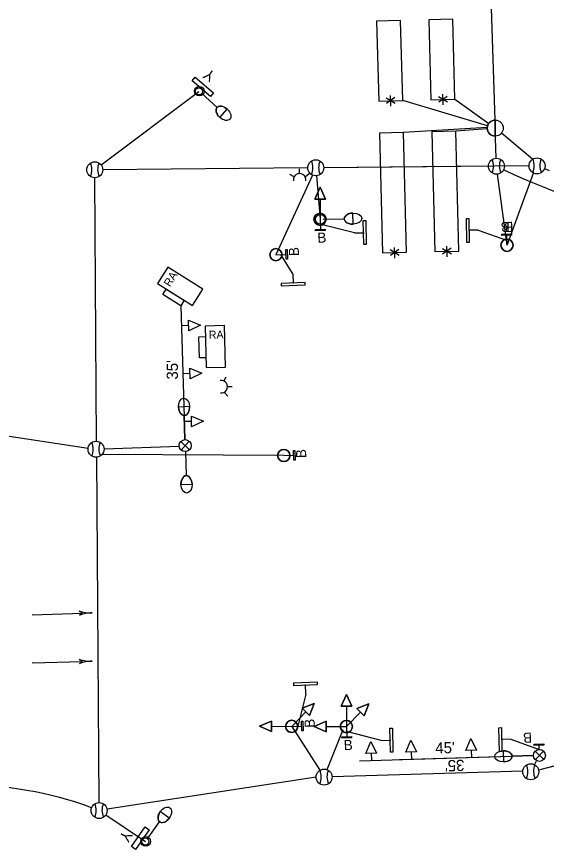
# Model space of a CAD drawing. Extents: x 596176 to 605330, y 332416 to 402398.
# Drawn here: x 603956.7 to 604089.1, y 339261.6 to 339469.9 of the extents above; entities that cross this region are included whole.
import ezdxf

# ---------------------------------------------------------------- set-up
doc = ezdxf.new("R2010")
doc.units = 0
for name, color, linetype in [('P_LTG', 7, 'Continuous'), ('P_SIG', 7, 'Continuous'), ('P_SIG_Bold', 7, 'Continuous'), ('P_SIG_Conduit', 7, 'Continuous'), ('P_SIG_Loops', 7, 'Continuous')]:
    doc.layers.add(name, color=color, linetype=linetype)

# ---------------------------------------------------------------- blocks, each defined once
blk = doc.blocks.new('LUMINAIRES')
at = {"layer": 'P_LTG'}
for p, q in [((4.32, 25.12), (-4.14, 25.12)), ((0.05, 2.3), (0.05, 18.44))]:
    blk.add_line(p, q, dxfattribs=at)
blk.add_circle((0.05, 0.15), 3.68, dxfattribs=at)
blk.add_ellipse((0.09, 25.12), major_axis=(0, 6.65), ratio=0.636439, dxfattribs=at)
blk.add_ellipse((0.09, 25.12), major_axis=(0, 6.65), ratio=0.636439, start_param=1.570796, end_param=4.712389, dxfattribs=at)
blk = doc.blocks.new('_U314')
at = {"layer": 'P_LTG'}
for p, q in [((4.32, 25.12), (-4.14, 25.12)), ((0.05, 2.3), (0.05, 18.44))]:
    blk.add_line(p, q, dxfattribs=at)
blk.add_ellipse((0.09, 25.12), major_axis=(0, 6.65), ratio=0.636439, dxfattribs=at)
blk.add_ellipse((0.09, 25.12), major_axis=(0, 6.65), ratio=0.636439, start_param=1.570796, end_param=4.712389, dxfattribs=at)
blk = doc.blocks.new('_U318')
at = {"layer": 'P_LTG'}
for p, q in [((4.32, 25.12), (-4.14, 25.12)), ((0.05, 2.3), (0.05, 18.44))]:
    blk.add_line(p, q, dxfattribs=at)
blk.add_ellipse((0.09, 25.12), major_axis=(0, 6.65), ratio=0.636439, dxfattribs=at)
blk.add_ellipse((0.09, 25.12), major_axis=(0, 6.65), ratio=0.636439, start_param=1.570796, end_param=4.712389, dxfattribs=at)

msp = doc.modelspace()

# ---------------------------------------------------------------- linework, layer by layer
at = {"layer": 'P_LTG'}
for p, q in [((603999.95, 339372.35), (603997.17, 339372.26)), ((603999.95, 339372.35), (603997.17, 339372.26)), ((603998.8, 339364.11), (603998.61, 339370.17)), ((603998.8, 339364.11), (603998.61, 339370.17)), ((603998.9, 339361.11), (603999.13, 339355.11)), ((603998.9, 339361.11), (603999.13, 339355.11)), ((603997.81, 339352.87), (604000.58, 339352.97)), ((603997.81, 339352.87), (604000.58, 339352.97))]:
    msp.add_line(p, q, dxfattribs=at)
for centre, major_axis in [((603998.56, 339372.3), (-0.07, 2.18)), ((603998.56, 339372.3), (-0.07, 2.18)), ((603999.19, 339352.92), (0.08, -2.18)), ((603999.19, 339352.92), (0.08, -2.18))]:
    msp.add_ellipse(centre, major_axis=major_axis, ratio=0.636439, dxfattribs=at)
for centre, major_axis in [((603998.56, 339372.3), (-0.07, 2.18)), ((603998.56, 339372.3), (-0.07, 2.18)), ((603999.19, 339352.92), (0.08, -2.18)), ((603999.19, 339352.92), (0.08, -2.18))]:
    msp.add_ellipse(centre, major_axis=major_axis, ratio=0.636439, start_param=1.570796, end_param=4.712389, dxfattribs=at)
at = {"layer": 'P_SIG'}
for p, q in [((604000.6, 339453.84), (604001.38, 339454.75)), ((604001.38, 339454.75), (604005.92, 339450.82)), ((604005.14, 339449.92), (604000.6, 339453.84)), ((604005.92, 339450.82), (604005.14, 339449.92)), ((604076.38, 339444.01), (604076.36, 339440.01)), ((604076.38, 339444.01), (604076.36, 339440.01)), ((604027.44, 339430.63), (604027.43, 339431.86)), ((604027.44, 339430.63), (604027.43, 339431.86)), ((604026.07, 339429.8), (604024.99, 339430.39)), ((604026.07, 339429.8), (604024.99, 339430.39)), ((604028.86, 339429.8), (604029.84, 339430.69)), ((604028.86, 339429.8), (604029.84, 339430.69)), ((604032.58, 339424.27), (604032.57, 339419.21)), ((604032.58, 339424.27), (604032.57, 339419.21)), ((604032.57, 339419.21), (604032.65, 339416.71)), ((604032.57, 339419.21), (604032.65, 339416.71)), ((604041.2, 339415.78), (604032.53, 339418.02)), ((604041.2, 339415.78), (604032.53, 339418.02)), ((604041.2, 339415.78), (604043.6, 339415.83)), ((604041.2, 339415.78), (604043.6, 339415.83)), ((604072.09, 339416.52), (604069.69, 339416.47)), ((604072.09, 339416.52), (604069.69, 339416.47)), ((604072.09, 339416.52), (604079.22, 339413.99)), ((604072.09, 339416.52), (604079.22, 339413.99)), ((604079.31, 339412.71), (604079.23, 339415.21)), ((604079.31, 339412.71), (604079.23, 339415.21)), ((604021.54, 339410.35), (604024.04, 339410.43)), ((604025.8, 339405.54), (604022.79, 339410.39)), ((604025.8, 339405.54), (604025.88, 339403.14)), ((603999.71, 339392.64), (603997.94, 339392.59)), ((603999.71, 339392.64), (603997.94, 339392.59)), ((604000.04, 339380.65), (603998.27, 339380.59)), ((604000.04, 339380.65), (603998.27, 339380.59)), ((604008.55, 339378.74), (604009.13, 339379.82)), ((604008.58, 339375.95), (604009.48, 339374.98)), ((604009.4, 339377.38), (604010.63, 339377.4)), ((604000.43, 339368.65), (603998.66, 339368.6)), ((604000.43, 339368.65), (603998.66, 339368.6)), ((604023.49, 339360.12), (604025.99, 339360.2)), ((603960.61, 339320.33), (603973.18, 339320.72)), ((603960.61, 339320.33), (603973.18, 339320.72)), ((603960.61, 339308.25), (603973.18, 339308.64)), ((603960.61, 339308.25), (603973.18, 339308.64)), ((604029, 339300.47), (604028.91, 339302.87)), ((604029, 339300.47), (604027, 339292.47)), ((604039.16, 339297.42), (604039.15, 339292.36)), ((604029.03, 339296), (604025.48, 339292.4)), ((604042.7, 339295.96), (604039.15, 339292.36)), ((604020.42, 339292.42), (604025.48, 339292.4)), ((604025.48, 339292.4), (604027.98, 339292.48)), ((604034.09, 339292.37), (604039.15, 339292.36)), ((604039.15, 339292.36), (604039.23, 339289.86)), ((604039.15, 339292.36), (604039.23, 339289.86)), ((604047.85, 339288.86), (604039.19, 339291.11)), ((604047.85, 339288.86), (604039.19, 339291.11)), ((604047.85, 339288.86), (604050.25, 339288.92)), ((604047.85, 339288.86), (604050.25, 339288.92)), ((604080.23, 339289.18), (604077.83, 339289.13)), ((604080.23, 339289.18), (604077.83, 339289.13)), ((604080.23, 339289.18), (604087.36, 339286.64)), ((604080.23, 339289.18), (604087.36, 339286.64)), ((604055.36, 339285.97), (604055.42, 339284.2)), ((604055.36, 339285.97), (604055.42, 339284.2)), ((604070.36, 339286.41), (604070.41, 339284.64)), ((604070.36, 339286.41), (604070.41, 339284.64)), ((604087.36, 339286.64), (604087.33, 339287.65)), ((604087.36, 339286.64), (604087.33, 339287.65)), ((604045.37, 339285.67), (604045.43, 339283.9)), ((603985.44, 339262.34), (603988.88, 339267.25)), ((603988.88, 339267.25), (603989.86, 339266.57)), ((603989.86, 339266.57), (603986.43, 339261.65)), ((603986.43, 339261.65), (603985.44, 339262.34))]:
    msp.add_line(p, q, dxfattribs=at)
for points in [[(604000.6, 339453.84), (604001.38, 339454.75), (604005.92, 339450.82), (604005.14, 339449.92)], [(604069.76, 339419.43), (604069.89, 339413.43), (604069.29, 339413.42), (604069.16, 339419.42)], [(604069.76, 339419.43), (604069.89, 339413.43), (604069.29, 339413.42), (604069.16, 339419.42)], [(604043.53, 339412.87), (604043.39, 339418.87), (604043.99, 339418.88), (604044.13, 339412.88)], [(604043.53, 339412.87), (604043.39, 339418.87), (604043.99, 339418.88), (604044.13, 339412.88)], [(604031.45, 339416.68), (604033.85, 339416.75), (604033.86, 339416.43), (604031.46, 339416.35)], [(604031.45, 339416.68), (604033.85, 339416.75), (604033.86, 339416.43), (604031.46, 339416.35)], [(604080.43, 339415.24), (604078.03, 339415.17), (604078.02, 339415.49), (604080.42, 339415.57)], [(604080.43, 339415.24), (604078.03, 339415.17), (604078.02, 339415.49), (604080.42, 339415.57)], [(604024.08, 339409.24), (604024, 339411.63), (604024.32, 339411.64), (604024.4, 339409.25)], [(604003.24, 339401.75), (603994.49, 339407.26), (603991.92, 339403.18), (604000.67, 339397.67)], [(604028.83, 339403.38), (604022.83, 339403.18), (604022.86, 339402.58), (604028.85, 339402.78)], [(603993.27, 339400.4), (603994.12, 339401.75), (603998.58, 339398.94), (603997.73, 339397.59)], [(604002.66, 339392.73), (603999.74, 339391.32), (603999.67, 339393.96)], [(604002.66, 339392.73), (603999.74, 339391.32), (603999.67, 339393.96)], [(604008.95, 339382.26), (604008.68, 339392.61), (604003.86, 339392.48), (604004.13, 339382.14)], [(604008.95, 339382.26), (604008.68, 339392.61), (604003.86, 339392.48), (604004.13, 339382.14)], [(604002.3, 339389.82), (604003.89, 339389.86), (604004.03, 339384.59), (604002.44, 339384.54)], [(604002.3, 339389.82), (604003.89, 339389.86), (604004.03, 339384.59), (604002.44, 339384.54)], [(604003, 339380.73), (604000.08, 339379.33), (604000, 339381.96)], [(604003, 339380.73), (604000.08, 339379.33), (604000, 339381.96)], [(604003.39, 339368.74), (604000.47, 339367.34), (604000.4, 339369.97)], [(604003.39, 339368.74), (604000.47, 339367.34), (604000.4, 339369.97)], [(604026.03, 339359), (604025.95, 339361.4), (604026.28, 339361.41), (604026.35, 339359.01)], [(604025.96, 339302.64), (604031.96, 339302.84), (604031.94, 339303.44), (604025.94, 339303.24)], [(604028.02, 339291.29), (604027.94, 339293.68), (604028.27, 339293.69), (604028.34, 339291.3)], [(604077.9, 339292.08), (604078.03, 339286.09), (604077.43, 339286.07), (604077.3, 339292.07)], [(604077.9, 339292.08), (604078.03, 339286.09), (604077.43, 339286.07), (604077.3, 339292.07)], [(604050.18, 339285.96), (604050.05, 339291.95), (604050.65, 339291.97), (604050.78, 339285.97)], [(604050.18, 339285.96), (604050.05, 339291.95), (604050.65, 339291.97), (604050.78, 339285.97)], [(604038.03, 339289.82), (604040.43, 339289.9), (604040.44, 339289.57), (604038.04, 339289.5)], [(604038.03, 339289.82), (604040.43, 339289.9), (604040.44, 339289.57), (604038.04, 339289.5)], [(604045.27, 339288.63), (604046.68, 339285.71), (604044.05, 339285.63)], [(604055.27, 339288.92), (604056.68, 339286.01), (604054.05, 339285.93)], [(604055.27, 339288.92), (604056.68, 339286.01), (604054.05, 339285.93)], [(604070.26, 339289.37), (604071.67, 339286.45), (604069.04, 339286.37)], [(604070.26, 339289.37), (604071.67, 339286.45), (604069.04, 339286.37)], [(604088.53, 339287.69), (604086.13, 339287.61), (604086.12, 339287.94), (604088.52, 339288.01)], [(604088.53, 339287.69), (604086.13, 339287.61), (604086.12, 339287.94), (604088.52, 339288.01)], [(603986.43, 339261.65), (603985.44, 339262.34), (603988.88, 339267.25), (603989.86, 339266.57)]]:
    msp.add_lwpolyline(points, close=True, dxfattribs=at)
for points in [[(604076.36, 339440.01), (604076.38, 339444.01)], [(604076.36, 339440.01), (604076.38, 339444.01)], [(604032.58, 339427.23), (604033.9, 339424.27), (604031.26, 339424.27), (604032.58, 339427.23)], [(604033.9, 339424.27), (604032.58, 339427.23), (604031.26, 339424.27), (604033.9, 339424.27)], [(604032.58, 339427.23), (604033.9, 339424.27), (604031.26, 339424.27), (604032.58, 339427.23)], [(604033.9, 339424.27), (604032.58, 339427.23), (604031.26, 339424.27), (604033.9, 339424.27)], [(603972.4, 339320.19), (603973.18, 339320.72), (603972.37, 339321.19)], [(603972.4, 339320.19), (603973.18, 339320.72), (603972.37, 339321.19)], [(603972.4, 339308.12), (603973.18, 339308.64), (603972.37, 339309.12)], [(603972.4, 339308.12), (603973.18, 339308.64), (603972.37, 339309.12)], [(604039.16, 339300.38), (604040.48, 339297.42), (604037.84, 339297.42), (604039.16, 339300.38)], [(604040.48, 339297.42), (604039.16, 339300.38), (604037.84, 339297.42), (604040.48, 339297.42)], [(604031.11, 339298.12), (604029.97, 339295.08), (604028.09, 339296.93), (604031.11, 339298.12)], [(604029.97, 339295.08), (604031.11, 339298.12), (604028.09, 339296.93), (604029.97, 339295.08)], [(604044.78, 339298.07), (604043.64, 339295.04), (604041.76, 339296.88), (604044.78, 339298.07)], [(604043.64, 339295.04), (604044.78, 339298.07), (604041.76, 339296.88), (604043.64, 339295.04)], [(604017.46, 339292.42), (604020.42, 339293.73), (604020.42, 339291.1), (604017.46, 339292.42)], [(604020.42, 339293.73), (604017.46, 339292.42), (604020.42, 339291.1), (604020.42, 339293.73)], [(604031.13, 339292.37), (604034.09, 339293.69), (604034.09, 339291.05), (604031.13, 339292.37)], [(604034.09, 339293.69), (604031.13, 339292.37), (604034.09, 339291.05), (604034.09, 339293.69)]]:
    msp.add_lwpolyline(points, dxfattribs=at)
for centre, radius in [((604002.29, 339451.19), 0.9), ((604076.37, 339442.01), 2), ((604076.37, 339442.01), 2), ((604031.5, 339432.08), 2), ((604031.5, 339432.08), 2), ((604076.68, 339432.48), 2), ((604086.81, 339432.57), 2), ((603976.26, 339431.6), 2), ((603976.26, 339431.6), 2), ((604032.57, 339419.21), 1.52), ((604032.57, 339419.21), 1.52), ((604032.57, 339419.21), 1.52), ((604032.57, 339419.21), 1.52), ((604032.57, 339419.21), 1.52), ((604032.57, 339419.21), 1.52), ((604079.31, 339412.71), 1.52), ((604079.31, 339412.71), 1.52), ((604021.54, 339410.35), 1.52), ((603976.56, 339361.71), 2), ((603976.56, 339361.71), 2), ((604023.49, 339360.12), 1.52), ((604025.48, 339292.4), 1.52), ((604025.48, 339292.4), 1.52), ((604025.48, 339292.4), 1.52), ((604025.48, 339292.4), 1.52), ((604025.48, 339292.4), 1.52), ((604025.48, 339292.4), 1.52), ((604039.15, 339292.36), 1.52), ((604039.15, 339292.36), 1.52), ((604039.15, 339292.36), 1.52), ((604039.15, 339292.36), 1.52), ((604039.15, 339292.36), 1.52), ((604039.15, 339292.36), 1.52), ((604039.15, 339292.36), 1.52), ((604039.15, 339292.36), 1.52), ((604039.15, 339292.36), 1.52), ((604039.15, 339292.36), 1.52), ((604033.59, 339279.73), 2), ((604033.59, 339279.73), 2), ((604085.24, 339281.05), 2), ((604085.24, 339281.05), 2), ((603977.34, 339271.35), 2), ((603977.34, 339271.35), 2), ((603988.89, 339263.61), 0.9)]:
    msp.add_circle(centre, radius, dxfattribs=at)
for centre, radius, start, end in [((604076.37, 339442.01), 2, 89.7008, 180), ((604076.37, 339442.01), 2, 89.7008, 180), ((604076.37, 339442.01), 2, 180, 269.7008), ((604076.37, 339442.01), 2, 180, 269.7008), ((604026.43, 339432.12), 4.36, 336.6741, 22.5272), ((604026.43, 339432.12), 4.36, 336.6741, 22.5272), ((604036.57, 339432.13), 4.36, 157.5751, 203.4282), ((604036.57, 339432.13), 4.36, 157.5751, 203.4282), ((604071.61, 339432.52), 4.36, 336.6741, 22.5272), ((604081.75, 339432.53), 4.36, 157.5751, 203.4282), ((604081.74, 339432.61), 4.36, 336.6741, 22.5272), ((604091.88, 339432.61), 4.36, 157.5751, 203.4282), ((603971.19, 339431.64), 4.36, 336.6741, 22.5272), ((603971.19, 339431.64), 4.36, 336.6741, 22.5272), ((603981.33, 339431.64), 4.36, 157.5751, 203.4282), ((603981.33, 339431.64), 4.36, 157.5751, 203.4282), ((604027.46, 339429.06), 1.58, 352.7774, 188.2849), ((604027.46, 339429.06), 1.58, 352.7774, 188.2849), ((604032.57, 339419.21), 1.52, 90, 270), ((604032.57, 339419.21), 1.52, 90, 270), ((604032.57, 339419.21), 1.52, 270, 90), ((604032.57, 339419.21), 1.52, 270, 90), ((604079.31, 339412.71), 1.52, 0, 180), ((604079.31, 339412.71), 1.52, 0, 180), ((604021.54, 339410.35), 1.52, 0, 180), ((604079.31, 339412.71), 1.52, 180, 0), ((604079.31, 339412.71), 1.52, 180, 0), ((604021.54, 339410.35), 1.52, 180, 0), ((604007.83, 339377.34), 1.58, 263.3712, 98.8787), ((603971.49, 339361.74), 4.36, 336.6741, 22.5272), ((603971.49, 339361.74), 4.36, 336.6741, 22.5272), ((603981.63, 339361.75), 4.36, 157.5751, 203.4282), ((603981.63, 339361.75), 4.36, 157.5751, 203.4282), ((604023.49, 339360.12), 1.52, 0, 180), ((604023.49, 339360.12), 1.52, 180, 0), ((603975.26, 339331.28), 10.49, 254.0031, 271.7654), ((603975.26, 339331.28), 10.49, 254.0031, 271.7654), ((603975.9, 339310.31), 10.49, 91.7654, 109.5278), ((603975.9, 339310.31), 10.49, 91.7654, 109.5278), ((603975.26, 339319.2), 10.49, 254.0031, 271.7654), ((603975.26, 339319.2), 10.49, 254.0031, 271.7654), ((603975.9, 339298.23), 10.49, 91.7654, 109.5278), ((603975.9, 339298.23), 10.49, 91.7654, 109.5278), ((604025.48, 339292.4), 1.52, 0, 180), ((604025.48, 339292.4), 1.52, 45.5187, 225.5187), ((604025.48, 339292.4), 1.52, 180, 0), ((604025.48, 339292.4), 1.52, 225.5187, 45.5187), ((604039.15, 339292.36), 1.52, 0, 180), ((604039.15, 339292.36), 1.52, 45.5187, 225.5187), ((604039.15, 339292.36), 1.52, 90, 270), ((604039.15, 339292.36), 1.52, 0, 180), ((604039.15, 339292.36), 1.52, 180, 0), ((604039.15, 339292.36), 1.52, 180, 0), ((604039.15, 339292.36), 1.52, 225.5187, 45.5187), ((604039.15, 339292.36), 1.52, 270, 90), ((604080.17, 339281.09), 4.36, 336.6741, 22.5272), ((604080.17, 339281.09), 4.36, 336.6741, 22.5272), ((604090.31, 339281.1), 4.36, 157.5751, 203.4282), ((604090.31, 339281.1), 4.36, 157.5751, 203.4282), ((604028.52, 339279.77), 4.36, 336.6741, 22.5272), ((604028.52, 339279.77), 4.36, 336.6741, 22.5272), ((604038.66, 339279.78), 4.36, 157.5751, 203.4282), ((604038.66, 339279.78), 4.36, 157.5751, 203.4282), ((603972.27, 339271.39), 4.36, 336.6741, 22.5272), ((603972.27, 339271.39), 4.36, 336.6741, 22.5272), ((603982.41, 339271.4), 4.36, 157.5751, 203.4282), ((603982.41, 339271.4), 4.36, 157.5751, 203.4282)]:
    msp.add_arc(centre, radius, start, end, dxfattribs=at)
at = {"layer": 'P_SIG_Bold'}
for p, q in [((603997.73, 339397.59), (603998.8, 339364.11)), ((603997.73, 339397.59), (603998.8, 339364.11)), ((603999.94, 339361.58), (603997.75, 339363.64)), ((603999.94, 339361.58), (603997.75, 339363.64)), ((603999.87, 339363.7), (603997.82, 339361.51)), ((603999.87, 339363.7), (603997.82, 339361.51)), ((604086.31, 339286.17), (604088.49, 339284.12)), ((604086.31, 339286.17), (604088.49, 339284.12)), ((604088.43, 339286.24), (604086.37, 339284.05)), ((604088.43, 339286.24), (604086.37, 339284.05)), ((604042.42, 339283.81), (604085.9, 339285.1)), ((604052.41, 339284.11), (604085.9, 339285.1))]:
    msp.add_line(p, q, dxfattribs=at)
for centre in [(603998.84, 339362.61), (603998.84, 339362.61), (604087.4, 339285.14), (604087.4, 339285.14)]:
    msp.add_circle(centre, 1.5, dxfattribs=at)
at = {"layer": 'P_SIG_Conduit'}
for p, q in [((603977.86, 339432.8), (604002.3, 339451.18)), ((603977.86, 339432.8), (604002.3, 339451.18)), ((604030.67, 339430.26), (604021.54, 339410.35)), ((604023.49, 339360.12), (603978.09, 339360.41)), ((604025.48, 339292.4), (604032.54, 339281.44)), ((604086.17, 339282.82), (604086.7, 339283.82)), ((604086.17, 339282.82), (604086.7, 339283.82)), ((604031.59, 339279.68), (603979.32, 339271.66)), ((604031.59, 339279.68), (603979.32, 339271.66)), ((604083.24, 339281.19), (604035.59, 339279.8)), ((604083.24, 339281.19), (604035.59, 339279.8)), ((603979.02, 339270.27), (603988.9, 339263.62)), ((603979.02, 339270.27), (603988.9, 339263.62))]:
    msp.add_line(p, q, dxfattribs=at)
for points in [[(604076.31, 339444.01), (604069.4, 339655.4)], [(604076.61, 339434.48), (604076.37, 339442.03)], [(604085.68, 339434.22), (604077.91, 339440.73)], [(604029.5, 339432.07), (603978.26, 339431.61)], [(604029.5, 339432.07), (603978.26, 339431.61)], [(604084.81, 339432.55), (604033.5, 339432.1)], [(604074.68, 339432.46), (604033.5, 339432.1)], [(604088.69, 339431.88), (604089.89, 339431.44)], [(603976.71, 339363.7), (603976.26, 339429.6)], [(603976.71, 339363.7), (603976.26, 339429.6)], [(604031.67, 339430.09), (604032.57, 339419.21)], [(604031.67, 339430.09), (604032.57, 339419.21)], [(604079.31, 339412.71), (604076.94, 339430.5)], [(604079.31, 339412.71), (604085.94, 339430.77)], [(603944.92, 339366.51), (603974.58, 339362.01)], [(603944.92, 339366.51), (603974.58, 339362.01)], [(603978.56, 339361.78), (603997.35, 339362.5)], [(603978.56, 339361.78), (603997.35, 339362.5)], [(603977.33, 339273.35), (603976.74, 339359.71)], [(603977.33, 339273.35), (603976.74, 339359.71)], [(604034.33, 339281.59), (604038.33, 339291.62)], [(604034.33, 339281.59), (604038.33, 339291.62)], [(604121.39, 339290.32), (604087.19, 339281.49)], [(604104.79, 339286.03), (604087.19, 339281.49)]]:
    msp.add_lwpolyline(points, dxfattribs=at)
for centre, radius, start, end in [((604149.94, 339581.75), 166.28, 244.5471, 259.1012), ((603944.03, 339186.98), 90.7, 69.7206, 90.9411), ((603944.03, 339186.98), 90.7, 69.7206, 90.9411)]:
    msp.add_arc(centre, radius, start, end, dxfattribs=at)
at = {"layer": 'P_SIG_Loops'}
for p, q in [((604063.35, 339447.82), (604063.28, 339450.49)), ((604063.35, 339447.82), (604063.28, 339450.49)), ((604051.35, 339448.16), (604049.14, 339449.52)), ((604051.35, 339448.16), (604049.14, 339449.52)), ((604051.3, 339449.62), (604049.17, 339448.13)), ((604051.3, 339449.62), (604049.17, 339448.13)), ((604050.28, 339447.48), (604050.21, 339450.16)), ((604050.28, 339447.48), (604050.21, 339450.16)), ((604050.23, 339448.85), (604053.23, 339448.93)), ((604050.23, 339448.85), (604053.23, 339448.93)), ((604074.46, 339442.58), (604053.23, 339448.93)), ((604074.46, 339442.58), (604053.23, 339448.93)), ((604064.42, 339448.5), (604062.21, 339449.85)), ((604064.42, 339448.5), (604062.21, 339449.85)), ((604064.37, 339449.95), (604062.23, 339448.46)), ((604064.37, 339449.95), (604062.23, 339448.46)), ((604063.29, 339449.19), (604066.29, 339449.27)), ((604063.29, 339449.19), (604066.29, 339449.27)), ((604066.29, 339449.27), (604074.75, 339443.18)), ((604066.29, 339449.27), (604074.75, 339443.18)), ((604074.38, 339442.15), (604053.43, 339440.94)), ((604074.38, 339442.15), (604053.43, 339440.94)), ((604074.38, 339441.86), (604066.5, 339441.26)), ((604074.38, 339441.86), (604066.5, 339441.26)), ((604052.33, 339410.18), (604050.12, 339411.53)), ((604052.33, 339410.18), (604050.12, 339411.53)), ((604052.28, 339411.63), (604050.15, 339410.14)), ((604052.28, 339411.63), (604050.15, 339410.14)), ((604051.26, 339409.5), (604051.19, 339412.17)), ((604051.26, 339409.5), (604051.19, 339412.17)), ((604051.21, 339410.87), (604054.21, 339410.95)), ((604051.21, 339410.87), (604054.21, 339410.95)), ((604065.4, 339410.5), (604063.19, 339411.85)), ((604065.4, 339410.5), (604063.19, 339411.85)), ((604065.35, 339411.96), (604063.21, 339410.47)), ((604065.35, 339411.96), (604063.21, 339410.47)), ((604064.33, 339409.82), (604064.26, 339412.5)), ((604064.33, 339409.82), (604064.26, 339412.5)), ((604064.27, 339411.19), (604067.27, 339411.27)), ((604064.27, 339411.19), (604067.27, 339411.27))]:
    msp.add_line(p, q, dxfattribs=at)
for points in [[(604066.29, 339449.27), (604065.78, 339469.26), (604059.78, 339469.1), (604060.29, 339449.11)], [(604066.29, 339449.27), (604065.78, 339469.26), (604059.78, 339469.1), (604060.29, 339449.11)], [(604053.23, 339448.93), (604052.71, 339468.93), (604046.71, 339468.77), (604047.23, 339448.78)], [(604053.23, 339448.93), (604052.71, 339468.93), (604046.71, 339468.77), (604047.23, 339448.78)], [(604054.21, 339410.95), (604053.43, 339440.94), (604047.44, 339440.78), (604048.21, 339410.79)], [(604054.21, 339410.95), (604053.43, 339440.94), (604047.44, 339440.78), (604048.21, 339410.79)], [(604067.27, 339411.27), (604066.5, 339441.26), (604060.5, 339441.11), (604061.27, 339411.12)], [(604067.27, 339411.27), (604066.5, 339441.26), (604060.5, 339441.11), (604061.27, 339411.12)]]:
    msp.add_lwpolyline(points, close=True, dxfattribs=at)

# ---------------------------------------------------------------- block references
at = {"layer": 'P_SIG'}
for name, p, xscale, yscale, rotation in [('LUMINAIRES', (604002.37, 339451.29), 0.32808333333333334, 0.3280833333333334, -132.40949839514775), ('LUMINAIRES', (604002.37, 339451.29), 0.3280833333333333, 0.3280833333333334, -132.40949839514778), ('LUMINAIRES', (604032.58, 339419.22), 0.3280833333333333, 0.32808333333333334, -88.71467693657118), ('LUMINAIRES', (604032.58, 339419.22), 0.3280833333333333, 0.32808333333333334, -88.71467693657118), ('_U314', (604086.65, 339285.1), 0.3280833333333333, 0.32808333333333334, 91.56622295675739), ('_U318', (604086.65, 339285.1), 0.3280833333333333, 0.32808333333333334, 91.56622295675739), ('LUMINAIRES', (603988.91, 339263.6), 0.32808333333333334, 0.3280833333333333, -35.803054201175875), ('LUMINAIRES', (603988.91, 339263.6), 0.32808333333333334, 0.3280833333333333, -35.803054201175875)]:
    msp.add_blockref(name, p, dxfattribs=dict(at, xscale=xscale, yscale=yscale, rotation=rotation))

# ---------------------------------------------------------------- texts
for s, height, rotation, p in [('Y', 2.8, 146.8745, (604006.67, 339455.71)), ('B', 2.52, 181.8373, (604079.96, 339418.58)), ('B', 2.52, 181.8373, (604080.86, 339418.59)), ('B', 2.52, 1.8373, (604031.94, 339413.32)), ('B', 2.52, 1.8373, (604031.94, 339413.32)), ('B', 2.52, 91.8335, (604027.32, 339410.04)), ('RA', 2, 57.81, (603995.05, 339402.17)), ('RA', 2, 1.5107, (604004.76, 339389.31)), ('RA', 2, 1.5107, (604004.76, 339389.31)), ('B', 2.52, 91.8335, (604029.13, 339359.52)), ('B', 2.52, 91.8335, (604031.26, 339292.09)), ('B', 2.52, 181.8373, (604085.52, 339290.88)), ('B', 2.52, 181.8373, (604085.52, 339290.88)), ('B', 2.52, 1.8373, (604038.53, 339286.44)), ('B', 2.52, 1.8373, (604038.53, 339286.44)), ('Y', 2.8, 242.8003, (603983.34, 339266.64))]:
    msp.add_text(s, height=height, rotation=rotation, dxfattribs=at).set_placement(p)
at = {"layer": 'P_SIG_Bold'}
for s, rotation, p in [("35'", 90, (603997.03, 339379.12)), ("35'", 90, (603997.03, 339379.12)), ("45'", 1.6965, (604061.42, 339285.59)), ("35'", 181.6965, (604068.62, 339284.08))]:
    msp.add_text(s, height=2.8, rotation=rotation, dxfattribs=at).set_placement(p)

doc.saveas('drawing.dxf')
